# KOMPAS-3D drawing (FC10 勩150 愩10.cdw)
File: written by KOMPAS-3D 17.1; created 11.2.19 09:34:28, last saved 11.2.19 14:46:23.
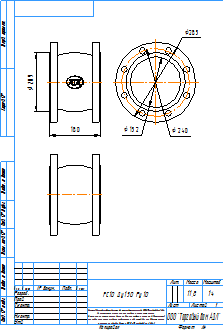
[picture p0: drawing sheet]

Sheet 1: A4, portrait

Title block, sheet 1: name: FC10 Ду150 Ру10; mass: 11,8; sheets: 1; sheet format: A4; stored path: \\adlc.lan\data\АДЛ_ПКД\3D-модели\ADL production\Гибкие вставки серии FC\FC10\KOMPAS 2D\FC10 Ду150 Ру10.cdw

Views: Вид 1
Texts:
  kka
  adl
  Рама для чертежей
  Лит-Масса-Масштаб
  Материал-Предприятие
  Масштаб
  Изм.
  Лист
  № докум.
  Подп.
  Дата
  Лит.
  Разраб.
  Пров.
  Т.контр.
  Листов
  Внимание! Данный продукт является объектом авторского права ООО «Торговый Дом АДЛ».
  Запрещается изменение, копирование, распространение
  (в том числе путем копирования на другие сайты и ресурсы в Интернете)
  или любое иное использование информации и объектов без предварительного
  согласия правообладателя (ООО «Торговый Дом АДЛ»).
  Н.контр.
  Утв.
  ООО "Торговый дом АДЛ"
  Изменение
  Номер документа
  Подпись
  Обозначение документа
  Наименование изделия
  Масса изделия по ГОСТ 2.109-73
  Порядковый номер листа
  Общее количество листов в документе
  Характер работы, выполненной лицом, подписавшим документ
  Наименование или индекс предприятия, выпускающего документ
  Инв. № подл.
  Подп. и дата
  Взам. инв. №
  Инв. № дубл.
  Инвентарный номер подлинника по ГОСТ 2.501-68
  Подпись принявшего подлинник в отдел технической документации
  Инвентарный номер подлинника, взамен которого выпущен данный подлинник
  Инвентарный номер дубликата по ГОСТ 2.502-68
  Подпись принявшего дубликат в отдел технической документации
  Справ. №
  Перв. примен.
  Обозначение документа, взамен или на основании которого выпущен данный документ
  Обозначение документа, в котором впервые записан данный документ
  Подпись лица, копировавшего чертеж
  Обозначение формата листа
  !Рама для чертежа
Dimensions and other numbers on the sheet: 180; 209; 152; 240; 285; 1:4; 1; 11,8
